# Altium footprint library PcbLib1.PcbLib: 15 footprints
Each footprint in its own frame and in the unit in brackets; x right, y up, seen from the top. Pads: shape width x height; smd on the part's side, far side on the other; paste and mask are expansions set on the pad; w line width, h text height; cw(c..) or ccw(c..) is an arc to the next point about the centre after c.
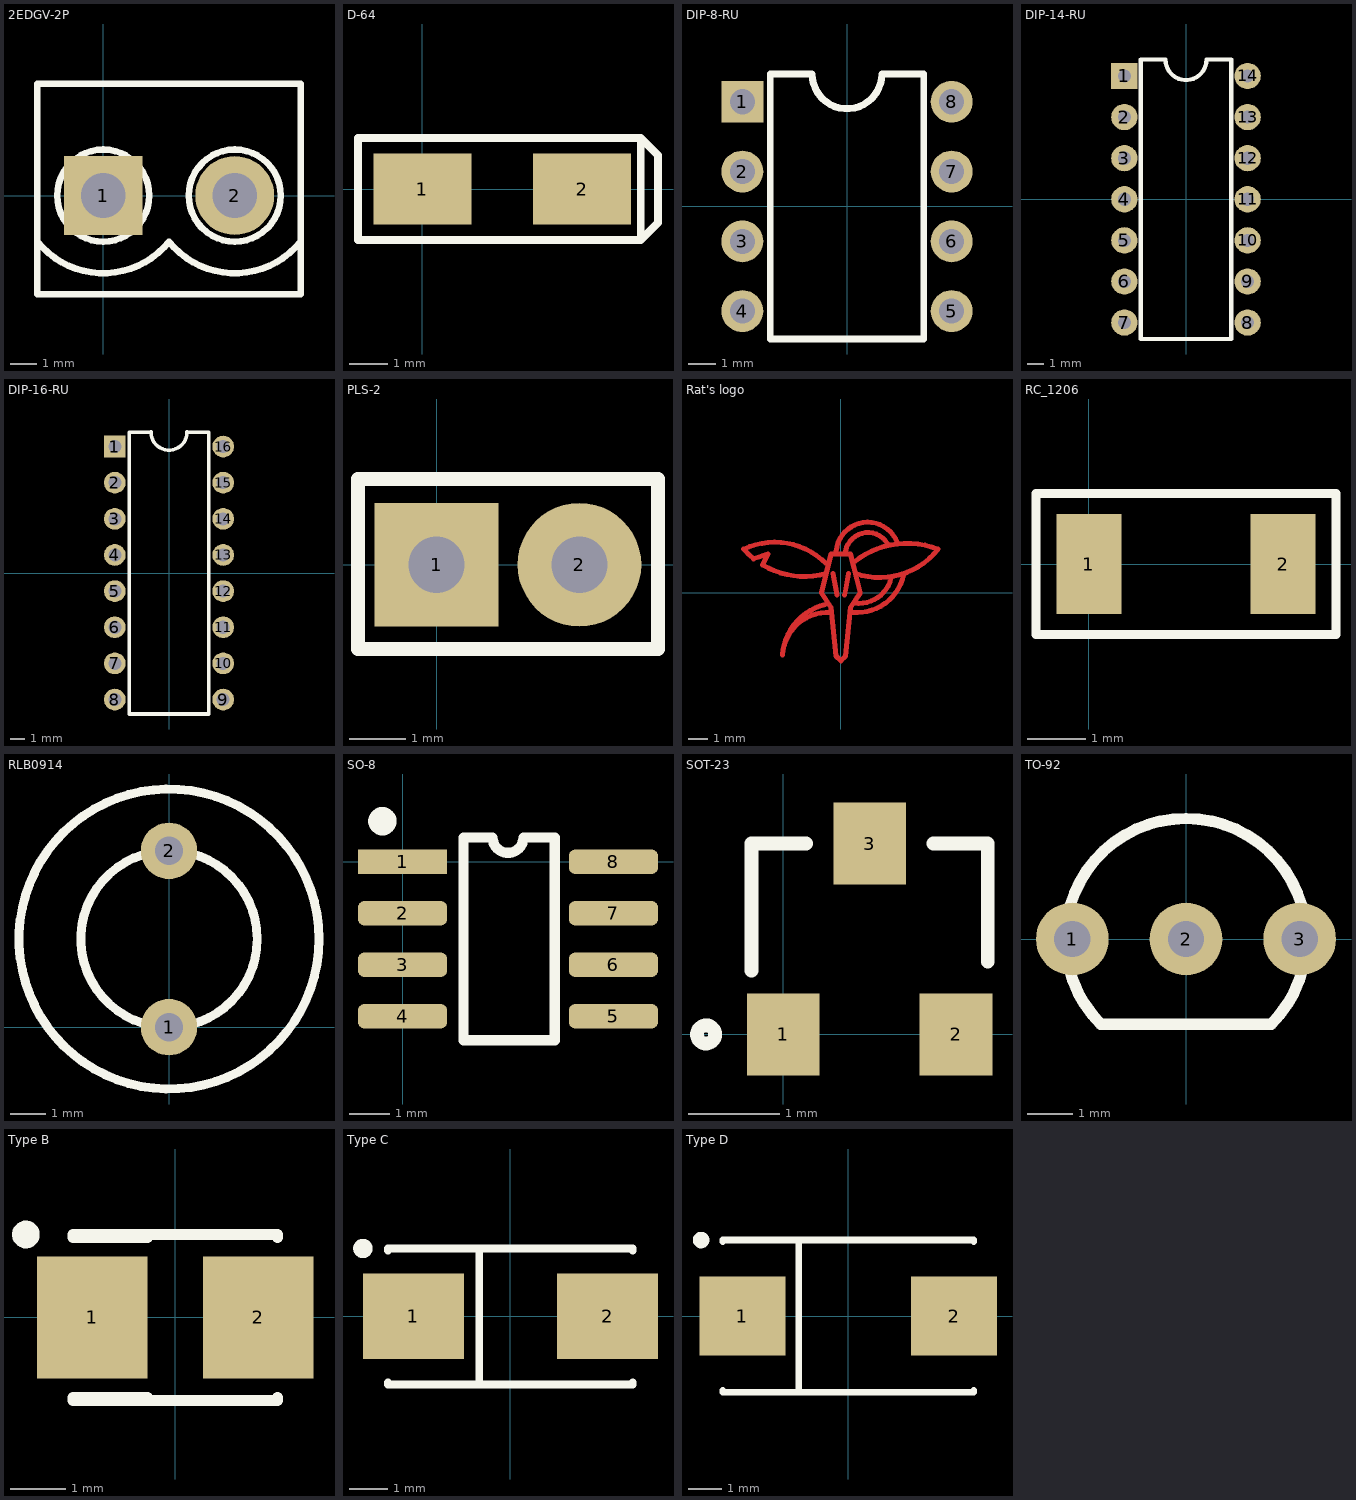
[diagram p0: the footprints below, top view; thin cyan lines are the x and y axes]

## 2EDGV-2P [mm]
height 10
pads (2):
  rect 3x3 hole 1.7: 1(0,0)
  round 3 hole 1.7: 2(5,0)
Top Overlay:
  circle w0.25: c5,0 r1.75
  circle w0.25: c0,0 r1.75
  lines w0.25: -2.5,-3.75 -2.5,4.25 7.5,4.25 7.5,-3.75 -2.5,-3.75
  lines w0.254: -2.499,-1.752 ccw(c0,0.25) 2.499,-1.752 ; 2.501,-1.752 ccw(c5,0.25) 7.499,-1.752
3D body: height 10.22, standoff -2.17, extent -2.725,-3.8 7.525,4

## D-64 [mm]
height 2.5
pads (2):
  rect 2.55x1.85 smd: 1(0,0) 2(4.15,0)
Top Overlay:
  lines w0.2: 5.675,-1.325 6.125,-0.875 6.125,0.875 5.675,1.325 ; 5.675,-1.325 -1.675,-1.325 -1.675,1.325 5.675,1.325 ; 5.675,-1.325 5.675,1.325
3D body: height 2.41, standoff -0.02, extent -0.65,-1.8 4.65,1.8

## DIP-8-RU [mm]
height 5
pads (8):
  rect 1.5x1.5 hole 0.9: 1(-3.75,3.75)
  round 1.5 hole 0.9: 2(-3.75,1.25) 3(-3.75,-1.25) 4(-3.75,-3.75) 5(3.75,-3.75) 6(3.75,-1.25) 7(3.75,1.25) 8(3.75,3.75)
Top Overlay:
  lines w0.25: -1.25,4.75 -2.75,4.75 -2.75,-4.75 2.75,-4.75 2.75,4.75 1.25,4.75
  lines w0.254: -1.25,4.75 ccw(c0,4.75) 1.25,4.75
3D body: height 5, standoff -3.5, extent -3.875,-5 3.875,5

## DIP-14-RU [mm]
height 5
pads (14):
  rect 1.6x1.6 hole 0.8: 1(-3.75,7.5)
  round 1.6 hole 0.8: 2(-3.75,5) 3(-3.75,2.5) 4(-3.75,0) 5(-3.75,-2.5) 6(-3.75,-5) 7(-3.75,-7.5) 8(3.75,-7.5) 9(3.75,-5) 10(3.75,-2.5) 11(3.75,0) 12(3.75,2.5) 13(3.75,5) 14(3.75,7.5)
Top Overlay:
  lines w0.25: -1.25,8.5 -2.75,8.5 -2.75,-8.5 2.75,-8.5 2.75,8.5 1.25,8.5
  lines w0.254: -1.25,8.5 ccw(c0,8.5) 1.25,8.5
3D body: height 4.5, standoff -3.5, extent -3.88,-9.05 3.88,9.05

## DIP-16-RU [mm]
height 5
pads (16):
  rect 1.5x1.5 hole 0.9: 1(-3.75,8.75)
  round 1.5 hole 0.9: 2(-3.75,6.25) 3(-3.75,3.75) 4(-3.75,1.25) 5(-3.75,-1.25) 6(-3.75,-3.75) 7(-3.75,-6.25) 8(-3.75,-8.75) 9(3.75,-8.75) 10(3.75,-6.25) 11(3.75,-3.75) 12(3.75,-1.25) 13(3.75,1.25) 14(3.75,3.75) 15(3.75,6.25) 16(3.75,8.75)
Top Overlay:
  lines w0.25: -1.25,9.75 -2.75,9.75 -2.75,-9.75 2.75,-9.75 2.75,9.75 1.25,9.75
  lines w0.254: -1.25,9.75 ccw(c0,9.75) 1.25,9.75
3D body: height 5.08, standoff -2.49, extent -3.935,-10 3.935,10

## PLS-2 [mm]
height 5
pads (2):
  rect 2.2x2.2 hole 1: 1(0,0)
  round 2.2 hole 1: 2(2.54,0)
Top Overlay:
  lines w0.25: -1.397,-1.5 -1.397,1.524 3.937,1.524 3.937,-1.5 -1.397,-1.5
3D body: height 8.54, standoff -3, extent -1.27,-1.27 3.81,1.27

## Rat's logo [mm]
Top Layer:
  lines w0.254: -4.516,1.786 cw(c-1.875,5.025) -5,2.25 cw(c-3.402,-1.109) -0.75,1.5 ; -4.5,1.75 -3.75,2 -4,1.5 ; -4.033,1.446 ccw(c-1.875,5.025) -0.75,1 ; -0.8,-0.6 ccw(c-0.153,-3.378) -3,-3.2 cw(c-0.65,-3.35) -0.5,-1 ; -0.4,1 -0.2,-0.1 ; -0.238,2.147 cw(c1.384,2.012) 2.9,2.6 ; 0.2,-0.1 0.4,1 ; 0.239,2.148 cw(c1.394,1.929) 2.395,2.546 ; 0.6,-1 ccw(c0.831,1.445) 3.23,0.923 ; 0.652,1.562 cw(c3.411,-1.797) 5,2.25 cw(c2,4.6) 0.75,1 ; 0.711,-0.52 ccw(c0.937,1.169) 2.6,0.8 ; -1,0 -0.5,2 0.5,2 1,0 0.5,-0.75 0.25,-3.25 0,-3.5 -0.25,-3.25 -0.5,-0.75 -1,0

## RC_1206 [mm]
height 1.5
pads (2):
  rect 1.1x1.7 smd: 1(0,0) 2(3.3,0)
Top Overlay:
  lines w0.15: -0.9,-1.2 -0.9,1.2 4.2,1.2 4.2,-1.2 -0.9,-1.2
3D body: height 1, standoff 0, extent 0.05,-0.8 3.25,0.8

## RLB0914 [mm]
height 8.5
pads (2):
  round 1.6 hole 0.8: 1(0,0) 2(0,5)
Top Overlay:
  circle w0.254: c0,2.5 r4.25
  circle w0.254: c0,2.5 r2.5
3D body: height 10, standoff -5, extent -4.35,-1.85 4.35,6.85

## SO-8 [mm]
height 2
pads (8):
  rect 2.2x0.6 smd: 1(0,0)
  rrect50% 2.2x0.6 smd: 2(0,-1.27) 3(0,-2.54) 4(0,-3.81) 5(5.2,-3.81) 6(5.2,-2.54) 7(5.2,-1.27) 8(5.2,0)
Top Overlay:
  circle w0.5: c-0.5,1 r0.1
  lines w0.254: 1.5,-4.4 1.5,0.6 2.219,0.6 ccw(c2.6,0.6) 2.981,0.6 3.75,0.6 3.75,0.2 3.75,-2.3 3.75,-4.4 1.5,-4.4
3D body: height 1.75, standoff 0, extent -0.475,-4.4 5.537,0.6

## SOT-23 [mm]
height 1.2
pads (3):
  rect 0.8x0.9 smd: 1(0,0) 2(1.9,0) 3(0.95,2.1)
Top Overlay:
  circle w0.15: c-0.85,0 r0.1
  lines w0.15: -0.35,0.7 -0.35,2.1 0.25,2.1 ; 1.65,2.1 2.25,2.1 2.25,0.8
3D body: height 1.06, standoff -0.04, extent -0.55,-0.3 2.45,2.2

## TO-92 [mm]
height 5
pads (3):
  round 1.6 hole 0.8: 1(-2.5,0) 2(0,0) 3(2.5,0)
Top Overlay:
  lines w0.25: -1.875,-1.875 cw(c0,0) 1.875,-1.875 -1.875,-1.875
3D body: height 9.7, standoff -2.7, extent -2.798,-1.746 2.798,2.184

## Type B [mm]
height 2.5
pads (2):
  rect 2x2.2 smd: 1(-1.5,0) 2(1.5,0)
Top Overlay:
  circle w0.25: c-2.7,1.5 r0.125
  lines w0.2: -1.85,-1.5 1.85,-1.5 1.85,-1.45 ; -1.85,-1.45 -0.5,-1.45 ; -1.85,1.45 -0.5,1.45 ; -1.85,1.5 1.85,1.5 1.85,1.45
3D body: height 1.89, standoff -0.02, extent -1.831,-1.4 1.832,1.4

## Type C [mm]
height 3.4
pads (2):
  rect 2.6x2.2 smd: 1(-2.5,0) 2(2.5,0)
Top Overlay:
  circle w0.25: c-3.8,1.75 r0.125
  lines w0.2: -3.15,-1.7 -3.15,-1.75 3.15,-1.75 3.15,-1.7 ; -3.15,1.7 -3.15,1.75 3.15,1.75 3.15,1.7 ; -0.8,-1.75 -0.8,1.75
3D body: height 2.79, standoff -0.04, extent -3.799,-1.8 3.799,1.713

## Type D [mm]
height 3.7
pads (2):
  rect 2.6x2.4 smd: 1(-3.2,0) 2(3.2,0)
Top Overlay:
  circle w0.25: c-4.45,2.3 r0.125
  lines w0.2: -3.8,-2.25 -3.8,-2.3 3.8,-2.3 3.8,-2.25 ; -3.8,2.25 -3.8,2.3 3.8,2.3 3.8,2.25 ; -1.5,-2.3 -1.5,2.3
3D body: height 3, standoff 0, extent -3.7,-2.225 3.7,2.225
